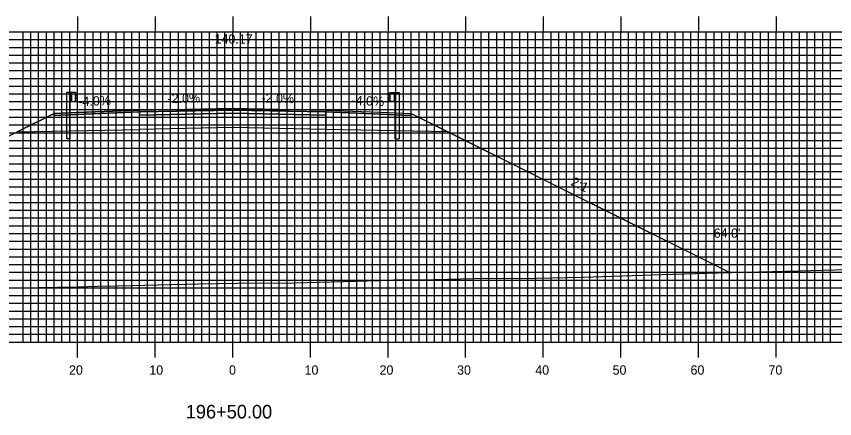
# Model space of a CAD drawing. Extents: x 1789730 to 1790074, y 442591 to 442811.
# Drawn here: x 1789868.3 to 1789973.7, y 442653.8 to 442705.7 of the extents above; entities that cross this region are included whole.
import ezdxf

# ---------------------------------------------------------------- set-up
doc = ezdxf.new("R2010")
doc.units = 0
for name, color, linetype in [('ANNOTATION', 7, 'Continuous'), ('D_Guardrail_Beam_Lt', 7, 'Continuous'), ('D_Guardrail_Beam_Rt', 7, 'Continuous'), ('D_Roadway_Centerline', 7, 'Continuous'), ('D_Roadway_Centerline_Text', 7, 'Continuous'), ('D_Roadway_Edge_Shoulder', 7, 'Continuous'), ('D_Roadway_Edge_TW', 7, 'Continuous'), ('D_Roadway_Pavement', 7, 'Continuous'), ('D_Roadway_SlopeLines', 7, 'Continuous'), ('D_Roadway_SubGrade', 7, 'Continuous'), ('D_Text_Standard', 7, 'Continuous'), ('H_V ANNOTATION', 7, 'Continuous'), ('MAJOR', 7, 'Continuous'), ('MINOR', 7, 'Continuous'), ('S_Roadway_Centerline', 7, 'Continuous')]:
    doc.layers.add(name, color=color, linetype=linetype)

msp = doc.modelspace()

# ---------------------------------------------------------------- linework, layer by layer
at = {"layer": 'D_Guardrail_Beam_Lt'}
for p, q in [((1789874.75, 442695.86), (1789874.75, 442689.86)), ((1789875.22, 442695.86), (1789874.75, 442695.86)), ((1789875.91, 442695.86), (1789875.22, 442695.86)), ((1789875.22, 442695.86), (1789875.22, 442694.69)), ((1789875.29, 442695.86), (1789875.29, 442694.69)), ((1789875.39, 442695.86), (1789875.39, 442694.69)), ((1789875.91, 442694.69), (1789875.91, 442695.86)), ((1789875.91, 442695.77), (1789875.99, 442695.76)), ((1789875.99, 442694.79), (1789875.91, 442694.77)), ((1789875.92, 442695.31), (1789875.92, 442695.24)), ((1789876.15, 442695.51), (1789875.95, 442695.37)), ((1789875.95, 442695.17), (1789876.15, 442695.04)), ((1789876, 442695.75), (1789876.15, 442695.65)), ((1789876.15, 442694.89), (1789876, 442694.79)), ((1789875.22, 442694.69), (1789875.91, 442694.69)), ((1789875.25, 442689.86), (1789875.25, 442694.69)), ((1789875.25, 442689.86), (1789874.75, 442689.86))]:
    msp.add_line(p, q, dxfattribs=at)
for centre, major_axis, start_param, end_param in [((1789876, 442695.31), (-0.0789, 0), 5.323254, 6.283185), ((1789876, 442695.24), (-0.0789, 0), 6.283185, 7.243116), ((1789875.98, 442695.72), (0.0417, 0), 0.959931, 1.376053), ((1789875.98, 442694.83), (0.0417, 0), 4.907132, 5.323254), ((1789876.09, 442695.58), (0.0877, 0), 5.323254, 7.243116), ((1789876.09, 442694.97), (0.0877, 0), 5.323254, 7.243116)]:
    msp.add_ellipse(centre, major_axis=major_axis, ratio=0.995501, start_param=start_param, end_param=end_param, dxfattribs=at)
at = {"layer": 'D_Guardrail_Beam_Rt'}
for p, q in [((1789916.45, 442695.86), (1789917.14, 442695.86)), ((1789916.45, 442694.69), (1789916.45, 442695.86)), ((1789916.97, 442695.86), (1789916.97, 442694.69)), ((1789917.08, 442695.86), (1789917.08, 442694.69)), ((1789917.14, 442695.86), (1789917.61, 442695.86)), ((1789917.14, 442695.86), (1789917.14, 442694.69)), ((1789917.61, 442695.86), (1789917.61, 442689.86)), ((1789916.36, 442695.75), (1789916.22, 442695.65)), ((1789916.22, 442695.51), (1789916.42, 442695.37)), ((1789916.42, 442695.17), (1789916.22, 442695.04)), ((1789916.22, 442694.89), (1789916.36, 442694.79)), ((1789916.45, 442695.77), (1789916.38, 442695.76)), ((1789916.38, 442694.79), (1789916.45, 442694.77)), ((1789916.45, 442695.31), (1789916.45, 442695.24)), ((1789917.14, 442694.69), (1789916.45, 442694.69)), ((1789917.12, 442689.86), (1789917.12, 442694.69)), ((1789917.12, 442689.86), (1789917.61, 442689.86))]:
    msp.add_line(p, q, dxfattribs=at)
for centre, major_axis, start_param, end_param in [((1789916.27, 442695.58), (-0.0877, 0), 5.323254, 7.243116), ((1789916.27, 442694.97), (-0.0877, 0), 5.323254, 7.243116), ((1789916.39, 442695.72), (-0.0417, 0), 4.907132, 5.323254), ((1789916.39, 442694.83), (-0.0417, 0), 0.959931, 1.376053), ((1789916.37, 442695.31), (0.0789, 0), 0, 0.959931), ((1789916.37, 442695.24), (0.0789, 0), 5.323254, 6.283185)]:
    msp.add_ellipse(centre, major_axis=major_axis, ratio=0.995501, start_param=start_param, end_param=end_param, dxfattribs=at)
at = {"layer": 'D_Roadway_Centerline'}
msp.add_lwpolyline([(1789826.5, 442669.81), (1789868.43, 442690.78), (1789873.18, 442693.15), (1789876.18, 442693.27), (1789884.18, 442693.59), (1789896.18, 442693.83), (1789908.18, 442693.59), (1789916.18, 442693.27), (1789919.18, 442693.15), (1789923.93, 442690.78), (1789960.22, 442672.63)], dxfattribs=at)
at = {"layer": 'D_Roadway_Edge_Shoulder'}
for points in [[(1789884.18, 442693.59), (1789876.18, 442693.27), (1789876.18, 442693.27), (1789873.18, 442693.15), (1789873.18, 442692.9), (1789884.18, 442693.34)], [(1789908.18, 442693.59), (1789916.18, 442693.27), (1789916.18, 442693.27), (1789919.18, 442693.15), (1789919.18, 442692.9), (1789908.18, 442693.34)]]:
    msp.add_lwpolyline(points, close=True, dxfattribs=at)
at = {"layer": 'D_Roadway_Edge_TW'}
msp.add_lwpolyline([(1789884.18, 442693.34), (1789884.18, 442693.59), (1789896.18, 442693.83), (1789908.18, 442693.59), (1789908.18, 442693.34), (1789896.18, 442693.58)], close=True, dxfattribs=at)
at = {"layer": 'D_Roadway_Pavement'}
msp.add_lwpolyline([(1789884.18, 442692.93), (1789884.18, 442693.34), (1789896.18, 442693.58), (1789908.18, 442693.34), (1789908.18, 442692.93), (1789896.18, 442693.17)], close=True, dxfattribs=at)
for points in [[(1789884.18, 442693.34), (1789884.18, 442692.93)], [(1789908.18, 442693.34), (1789908.18, 442692.93)]]:
    msp.add_lwpolyline(points, dxfattribs=at)
at = {"layer": 'D_Roadway_SlopeLines'}
for points in [[(1789873.18, 442693.15), (1789826.5, 442669.81)], [(1789919.18, 442693.15), (1789960.22, 442672.63)]]:
    msp.add_lwpolyline(points, dxfattribs=at)
at = {"layer": 'D_Roadway_SubGrade'}
for points in [[(1789884.18, 442692.93), (1789884.18, 442693.34), (1789873.18, 442692.9), (1789873.18, 442693.15), (1789868.43, 442690.78), (1789884.18, 442691.09)], [(1789884.18, 442691.09), (1789884.18, 442693.34), (1789884.18, 442692.93), (1789896.18, 442693.17), (1789908.18, 442692.93), (1789908.18, 442693.34), (1789908.18, 442691.09), (1789896.18, 442691.33)], [(1789908.18, 442692.93), (1789908.18, 442693.34), (1789919.18, 442692.9), (1789919.18, 442693.15), (1789923.93, 442690.78), (1789908.18, 442691.09)]]:
    msp.add_lwpolyline(points, close=True, dxfattribs=at)
at = {"layer": 'MAJOR'}
for p, q in [((1789876.18, 442705.67), (1789876.18, 442703.67)), ((1789886.18, 442705.67), (1789886.18, 442703.67)), ((1789896.18, 442705.67), (1789896.18, 442703.67)), ((1789906.18, 442705.67), (1789906.18, 442703.67)), ((1789916.18, 442705.67), (1789916.18, 442703.67)), ((1789926.18, 442705.67), (1789926.18, 442703.67)), ((1789936.18, 442705.67), (1789936.18, 442703.67)), ((1789946.18, 442705.67), (1789946.18, 442703.67)), ((1789956.18, 442705.67), (1789956.18, 442703.67)), ((1789966.18, 442705.67), (1789966.18, 442703.67)), ((1789756.18, 442703.67), (1790036.18, 442703.67)), ((1789756.18, 442703.67), (1790036.18, 442703.67)), ((1789876.18, 442663.67), (1789876.18, 442703.67)), ((1789886.18, 442663.67), (1789886.18, 442703.67)), ((1789896.18, 442663.67), (1789896.18, 442703.67)), ((1789906.18, 442663.67), (1789906.18, 442703.67)), ((1789916.18, 442663.67), (1789916.18, 442703.67)), ((1789926.18, 442663.67), (1789926.18, 442703.67)), ((1789936.18, 442663.67), (1789936.18, 442703.67)), ((1789946.18, 442663.67), (1789946.18, 442703.67)), ((1789956.18, 442663.67), (1789956.18, 442703.67)), ((1789966.18, 442663.67), (1789966.18, 442703.67)), ((1789756.18, 442698.67), (1790036.18, 442698.67)), ((1789756.18, 442693.67), (1790036.18, 442693.67)), ((1789756.18, 442688.67), (1790036.18, 442688.67)), ((1789756.18, 442683.67), (1790036.18, 442683.67)), ((1789756.18, 442678.67), (1790036.18, 442678.67)), ((1789756.18, 442673.67), (1790036.18, 442673.67)), ((1789756.18, 442668.67), (1790036.18, 442668.67)), ((1789756.18, 442663.67), (1790036.18, 442663.67)), ((1789756.18, 442663.67), (1790036.18, 442663.67)), ((1789876.18, 442661.66), (1789876.18, 442663.67)), ((1789886.18, 442661.66), (1789886.18, 442663.67)), ((1789896.18, 442661.66), (1789896.18, 442663.67)), ((1789906.18, 442661.66), (1789906.18, 442663.67)), ((1789916.18, 442661.66), (1789916.18, 442663.67)), ((1789926.18, 442661.66), (1789926.18, 442663.67)), ((1789936.18, 442661.66), (1789936.18, 442663.67)), ((1789946.18, 442661.66), (1789946.18, 442663.67)), ((1789956.18, 442661.66), (1789956.18, 442663.67)), ((1789966.18, 442661.66), (1789966.18, 442663.67))]:
    msp.add_line(p, q, dxfattribs=at)
at = {"layer": 'MINOR'}
for p, q in [((1789869.18, 442663.67), (1789869.18, 442703.67)), ((1789870.18, 442663.67), (1789870.18, 442703.67)), ((1789871.18, 442663.67), (1789871.18, 442703.67)), ((1789872.18, 442663.67), (1789872.18, 442703.67)), ((1789873.18, 442663.67), (1789873.18, 442703.67)), ((1789874.18, 442663.67), (1789874.18, 442703.67)), ((1789875.18, 442663.67), (1789875.18, 442703.67)), ((1789877.18, 442663.67), (1789877.18, 442703.67)), ((1789878.18, 442663.67), (1789878.18, 442703.67)), ((1789879.18, 442663.67), (1789879.18, 442703.67)), ((1789880.18, 442663.67), (1789880.18, 442703.67)), ((1789881.18, 442663.67), (1789881.18, 442703.67)), ((1789882.18, 442663.67), (1789882.18, 442703.67)), ((1789883.18, 442663.67), (1789883.18, 442703.67)), ((1789884.18, 442663.67), (1789884.18, 442703.67)), ((1789885.18, 442663.67), (1789885.18, 442703.67)), ((1789887.18, 442663.67), (1789887.18, 442703.67)), ((1789888.18, 442663.67), (1789888.18, 442703.67)), ((1789889.18, 442663.67), (1789889.18, 442703.67)), ((1789890.18, 442663.67), (1789890.18, 442703.67)), ((1789891.18, 442663.67), (1789891.18, 442703.67)), ((1789892.18, 442663.67), (1789892.18, 442703.67)), ((1789893.18, 442663.67), (1789893.18, 442703.67)), ((1789894.18, 442663.67), (1789894.18, 442703.67)), ((1789895.18, 442663.67), (1789895.18, 442703.67)), ((1789897.18, 442663.67), (1789897.18, 442703.67)), ((1789898.18, 442663.67), (1789898.18, 442703.67)), ((1789899.18, 442663.67), (1789899.18, 442703.67)), ((1789900.18, 442663.67), (1789900.18, 442703.67)), ((1789901.18, 442663.67), (1789901.18, 442703.67)), ((1789902.18, 442663.67), (1789902.18, 442703.67)), ((1789903.18, 442663.67), (1789903.18, 442703.67)), ((1789904.18, 442663.67), (1789904.18, 442703.67)), ((1789905.18, 442663.67), (1789905.18, 442703.67)), ((1789907.18, 442663.67), (1789907.18, 442703.67)), ((1789908.18, 442663.67), (1789908.18, 442703.67)), ((1789909.18, 442663.67), (1789909.18, 442703.67)), ((1789910.18, 442663.67), (1789910.18, 442703.67)), ((1789911.18, 442663.67), (1789911.18, 442703.67)), ((1789912.18, 442663.67), (1789912.18, 442703.67)), ((1789913.18, 442663.67), (1789913.18, 442703.67)), ((1789914.18, 442663.67), (1789914.18, 442703.67)), ((1789915.18, 442663.67), (1789915.18, 442703.67)), ((1789917.18, 442663.67), (1789917.18, 442703.67)), ((1789918.18, 442663.67), (1789918.18, 442703.67)), ((1789919.18, 442663.67), (1789919.18, 442703.67)), ((1789920.18, 442663.67), (1789920.18, 442703.67)), ((1789921.18, 442663.67), (1789921.18, 442703.67)), ((1789922.18, 442663.67), (1789922.18, 442703.67)), ((1789923.18, 442663.67), (1789923.18, 442703.67)), ((1789924.18, 442663.67), (1789924.18, 442703.67)), ((1789925.18, 442663.67), (1789925.18, 442703.67)), ((1789927.18, 442663.67), (1789927.18, 442703.67)), ((1789928.18, 442663.67), (1789928.18, 442703.67)), ((1789929.18, 442663.67), (1789929.18, 442703.67)), ((1789930.18, 442663.67), (1789930.18, 442703.67)), ((1789931.18, 442663.67), (1789931.18, 442703.67)), ((1789932.18, 442663.67), (1789932.18, 442703.67)), ((1789933.18, 442663.67), (1789933.18, 442703.67)), ((1789934.18, 442663.67), (1789934.18, 442703.67)), ((1789935.18, 442663.67), (1789935.18, 442703.67)), ((1789937.18, 442663.67), (1789937.18, 442703.67)), ((1789938.18, 442663.67), (1789938.18, 442703.67)), ((1789939.18, 442663.67), (1789939.18, 442703.67)), ((1789940.18, 442663.67), (1789940.18, 442703.67)), ((1789941.18, 442663.67), (1789941.18, 442703.67)), ((1789942.18, 442663.67), (1789942.18, 442703.67)), ((1789943.18, 442663.67), (1789943.18, 442703.67)), ((1789944.18, 442663.67), (1789944.18, 442703.67)), ((1789945.18, 442663.67), (1789945.18, 442703.67)), ((1789947.18, 442663.67), (1789947.18, 442703.67)), ((1789948.18, 442663.67), (1789948.18, 442703.67)), ((1789949.18, 442663.67), (1789949.18, 442703.67)), ((1789950.18, 442663.67), (1789950.18, 442703.67)), ((1789951.18, 442663.67), (1789951.18, 442703.67)), ((1789952.18, 442663.67), (1789952.18, 442703.67)), ((1789953.18, 442663.67), (1789953.18, 442703.67)), ((1789954.18, 442663.67), (1789954.18, 442703.67)), ((1789955.18, 442663.67), (1789955.18, 442703.67)), ((1789957.18, 442663.67), (1789957.18, 442703.67)), ((1789958.18, 442663.67), (1789958.18, 442703.67)), ((1789959.18, 442663.67), (1789959.18, 442703.67)), ((1789960.18, 442663.67), (1789960.18, 442703.67)), ((1789961.18, 442663.67), (1789961.18, 442703.67)), ((1789962.18, 442663.67), (1789962.18, 442703.67)), ((1789963.18, 442663.67), (1789963.18, 442703.67)), ((1789964.18, 442663.67), (1789964.18, 442703.67)), ((1789965.18, 442663.67), (1789965.18, 442703.67)), ((1789967.18, 442663.67), (1789967.18, 442703.67)), ((1789968.18, 442663.67), (1789968.18, 442703.67)), ((1789969.18, 442663.67), (1789969.18, 442703.67)), ((1789970.18, 442663.67), (1789970.18, 442703.67)), ((1789971.18, 442663.67), (1789971.18, 442703.67)), ((1789972.18, 442663.67), (1789972.18, 442703.67)), ((1789973.18, 442663.67), (1789973.18, 442703.67)), ((1789756.18, 442702.67), (1790036.18, 442702.67)), ((1789756.18, 442701.67), (1790036.18, 442701.67)), ((1789756.18, 442700.67), (1790036.18, 442700.67)), ((1789756.18, 442699.67), (1790036.18, 442699.67)), ((1789756.18, 442697.67), (1790036.18, 442697.67)), ((1789756.18, 442696.67), (1790036.18, 442696.67)), ((1789756.18, 442695.67), (1790036.18, 442695.67)), ((1789756.18, 442694.67), (1790036.18, 442694.67)), ((1789756.18, 442692.67), (1790036.18, 442692.67)), ((1789756.18, 442691.67), (1790036.18, 442691.67)), ((1789756.18, 442690.67), (1790036.18, 442690.67)), ((1789756.18, 442689.67), (1790036.18, 442689.67)), ((1789756.18, 442687.67), (1790036.18, 442687.67)), ((1789756.18, 442686.67), (1790036.18, 442686.67)), ((1789756.18, 442685.67), (1790036.18, 442685.67)), ((1789756.18, 442684.67), (1790036.18, 442684.67)), ((1789756.18, 442682.67), (1790036.18, 442682.67)), ((1789756.18, 442681.67), (1790036.18, 442681.67)), ((1789756.18, 442680.67), (1790036.18, 442680.67)), ((1789756.18, 442679.67), (1790036.18, 442679.67)), ((1789756.18, 442677.67), (1790036.18, 442677.67)), ((1789756.18, 442676.67), (1790036.18, 442676.67)), ((1789756.18, 442675.67), (1790036.18, 442675.67)), ((1789756.18, 442674.67), (1790036.18, 442674.67)), ((1789756.18, 442672.67), (1790036.18, 442672.67)), ((1789756.18, 442671.67), (1790036.18, 442671.67)), ((1789756.18, 442670.67), (1790036.18, 442670.67)), ((1789756.18, 442669.67), (1790036.18, 442669.67)), ((1789756.18, 442667.67), (1790036.18, 442667.67)), ((1789756.18, 442666.67), (1790036.18, 442666.67)), ((1789756.18, 442665.67), (1790036.18, 442665.67)), ((1789756.18, 442664.67), (1790036.18, 442664.67))]:
    msp.add_line(p, q, dxfattribs=at)
at = {"layer": 'S_Roadway_Centerline'}
msp.add_lwpolyline([(1789860.76, 442670.53), (1789876.17, 442670.81), (1789878.75, 442670.86), (1789881.36, 442670.92), (1789891.76, 442671.17), (1789896.83, 442671.25), (1789904.2, 442671.29), (1789915.04, 442671.61), (1789916.87, 442671.68), (1789920.47, 442671.7), (1789928.96, 442671.91), (1789933.37, 442671.87), (1789941.33, 442672.04), (1789951.49, 442672.38), (1789958.65, 442672.6), (1789965.65, 442672.76), (1789969.15, 442672.87), (1789978.48, 442673.13)], dxfattribs=at)

# ---------------------------------------------------------------- texts
at = {"layer": 'ANNOTATION'}
for s, rotation, p in [('-4.0%', 2.2906, (1789876.31, 442694.08)), ('-2.0%', 1.1458, (1789887.79, 442694.47)), ('-2.0%', 358.8542, (1789899.87, 442694.56)), ('-4.0%', 357.7094, (1789911.47, 442694.26)), ('2:1', 333.4349, (1789939.63, 442683.96))]:
    msp.add_text(s, height=1.2, rotation=rotation, dxfattribs=at).set_placement(p)
at = {"layer": 'D_Roadway_Centerline'}
for s in ['C', 'L']:
    msp.add_text(s, height=0.0146, dxfattribs=at).set_placement((1789896.18, 442693.83))
at = {"layer": 'D_Roadway_Centerline_Text'}
msp.add_text('140.17', height=1.2, dxfattribs=at).set_placement((1789893.84, 442702.16))
at = {"layer": 'D_Text_Standard'}
msp.add_text("64.0'", height=1.2, dxfattribs=at).set_placement((1789958.13, 442677.12))
at = {"layer": 'H_V ANNOTATION'}
for s, height, p in [('20', 1.2, (1789875.09, 442659.47)), ('10', 1.2, (1789885.43, 442659.47)), ('0', 1.2, (1789895.7, 442659.47)), ('10', 1.2, (1789905.43, 442659.47)), ('20', 1.2, (1789915.09, 442659.47)), ('30', 1.2, (1789925.08, 442659.47)), ('40', 1.2, (1789935.15, 442659.47)), ('50', 1.2, (1789945.11, 442659.47)), ('60', 1.2, (1789955.15, 442659.47)), ('70', 1.2, (1789965.19, 442659.47)), ('196+50.00', 1.75, (1789890.13, 442653.82))]:
    msp.add_text(s, height=height, dxfattribs=at).set_placement(p)

doc.saveas('drawing.dxf')
